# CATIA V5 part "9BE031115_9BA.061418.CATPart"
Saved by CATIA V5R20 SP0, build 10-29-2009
Part number: 9BE031115_9BA.061418
Revision: ANY
Definition: UNKNOWN
Nomenclature: 9BE031115_9BA.061418
Source: Unknown
Bounding box of the stored display mesh (mm): x -7.312 to 7.312, y 0 to 25.5, z -7.5 to 7.5
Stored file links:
  C:\Users\Utente\Desktop\IO LAVORO\3D X SITO CF\CUMSA\3D files BE\BE 031115\9BE031115_9BA.061418.CATPart
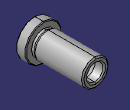
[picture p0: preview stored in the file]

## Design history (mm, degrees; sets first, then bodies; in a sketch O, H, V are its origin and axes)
Body1 "Chaflán4" (main body)
  Solid1: solid without history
